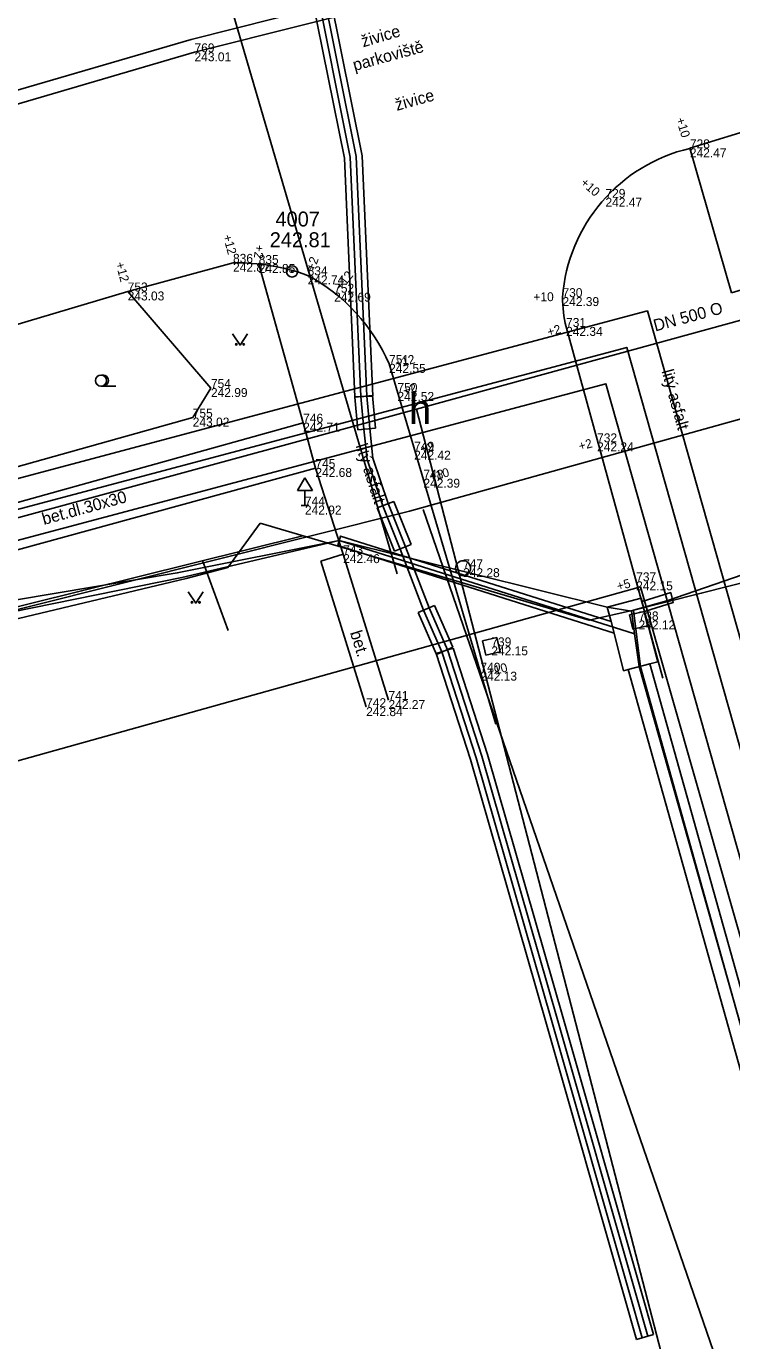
# Model space of a CAD drawing. Extents: x -599432 to -598680, y -1159407 to -1158632.
# Drawn here: x -599111.08 to -599087.44, y -1158969.78 to -1158925.7 of the extents above; entities that cross this region are included whole.
import ezdxf

# ---------------------------------------------------------------- set-up
doc = ezdxf.new("R2010")
doc.units = 0
for name, color, linetype in [('0001 VY - Body PBP', 7, 'Continuous'), ('0002 VY - Body PBP - čísla', 7, 'Continuous'), ('0003 VY - Body PBP - výšky', 7, 'Continuous'), ('0004 VY - Body podrobné', 7, 'Continuous'), ('0005 VY - Body podrobné - čísla', 7, 'Continuous'), ('0006 VY - Body podrobné - výšky', 7, 'Continuous'), ('0024 ZA - Podezdívka', 7, 'Continuous'), ('0025 ZA - Opěrná zeď', 7, 'Continuous'), ('0027 ZA - Silnice_cesta zpevněná', 7, 'Continuous'), ('0030 ZA - Chodník', 7, 'Continuous'), ('0031 ZA - Ostatní rozhraní', 7, 'Continuous'), ('0032 TE - Popis povrchu', 7, 'Continuous'), ('0034 ZA - Kultury - značky', 7, 'Continuous'), ('0038 ZA - Hranice souvislého porostu', 7, 'Continuous'), ('0062 ZA - Doprava - dopravní značky', 7, 'Continuous'), ('0073 TE - Výška obrubníků a zdí', 7, 'Continuous'), ('0074 TE - Vysvětlivky', 7, 'Continuous'), ('0075 ZA - BVK - kanalizace - buňky', 7, 'Continuous'), ('0200 PV - BVK - kanalizace - buňky', 7, 'Continuous'), ('0201 PV - BVK - kanalizace - popis', 7, 'Continuous'), ('0206 PV - BVK - kanalizace - jednotná', 7, 'Continuous'), ('0214 PV - BVK - vodovod - pitná', 7, 'Continuous'), ('0221 PV - BVK - vodovod - zrušený', 7, 'Continuous'), ('0254 PV - TB - horkovod - vedení', 7, 'Continuous'), ('0255 PV - TB - horkovod - okraj', 7, 'Continuous'), ('0354 PV - EON - VN', 7, 'Continuous'), ('0367 PV - EON - VN chránička', 7, 'Continuous'), ('0454 PV - O2 - kabel zaměřený', 7, 'Continuous'), ('0455 PV - O2 - kabel nezaměřený', 7, 'Continuous'), ('0457 PV - O2 - kabelovod', 7, 'Continuous'), ('0502 PV - UPC - vedení', 7, 'Continuous'), ('0550 PV - UPC - přípojka', 7, 'Continuous'), ('0552 PV - OT VUT', 7, 'Continuous'), ('0602 PV - FASTER', 7, 'Continuous'), ('0703 PV - DIAL TELECOM optický kabel', 7, 'Continuous'), ('0750 ZA - nerozlišené sítě - buňky', 7, 'Continuous')]:
    doc.layers.add(name, color=color, linetype=linetype)

msp = doc.modelspace()

# ---------------------------------------------------------------- linework, layer by layer
at = {"layer": '0001 VY - Body PBP'}
for radius in [0.188, 0.00896]:
    msp.add_circle((-599102.17, -1158933.92), radius, dxfattribs=at)
at = {"layer": '0004 VY - Body podrobné'}
for p, q in [((-599105.44, -1158926.57), (-599105.44, -1158926.57)), ((-599088.84, -1158929.79), (-599088.84, -1158929.79)), ((-599091.67, -1158931.45), (-599091.67, -1158931.45)), ((-599104.15, -1158933.63), (-599104.15, -1158933.63)), ((-599103.29, -1158933.67), (-599103.29, -1158933.67)), ((-599101.65, -1158934.05), (-599101.65, -1158934.05)), ((-599107.68, -1158934.59), (-599107.68, -1158934.59)), ((-599100.76, -1158934.63), (-599100.76, -1158934.63)), ((-599093.11, -1158934.78), (-599093.11, -1158934.78)), ((-599087.45, -1158934.64), (-599087.45, -1158934.64)), ((-599092.99, -1158935.78), (-599092.99, -1158935.78)), ((-599098.92, -1158937.02), (-599098.92, -1158937.02)), ((-599104.89, -1158937.83), (-599104.89, -1158937.83)), ((-599098.64, -1158937.96), (-599098.64, -1158937.96)), ((-599105.5, -1158938.82), (-599105.5, -1158938.82)), ((-599101.8, -1158938.99), (-599101.8, -1158938.99)), ((-599091.95, -1158939.65), (-599091.95, -1158939.65)), ((-599098.08, -1158939.93), (-599098.08, -1158939.93)), ((-599101.39, -1158940.51), (-599101.39, -1158940.51)), ((-599097.77, -1158940.87), (-599097.77, -1158940.87)), ((-599101.74, -1158941.77), (-599101.74, -1158941.77)), ((-599100.46, -1158943.4), (-599100.46, -1158943.4)), ((-599096.44, -1158943.87), (-599096.44, -1158943.87)), ((-599090.64, -1158944.31), (-599090.64, -1158944.31)), ((-599090.56, -1158945.621), (-599090.56, -1158945.621)), ((-599095.494, -1158946.491), (-599095.494, -1158946.491)), ((-599095.86, -1158947.34), (-599095.86, -1158947.34)), ((-599099.69, -1158948.53), (-599099.69, -1158948.53)), ((-599098.94, -1158948.29), (-599098.94, -1158948.29))]:
    msp.add_line(p, q, dxfattribs=at)
at = {"layer": '0024 ZA - Podezdívka'}
for p, q in [((-599105.558, -1158926.136), (-599091.888, -1158922.688)), ((-599105.44, -1158926.57), (-599091.76, -1158923.12)), ((-599126.554, -1158932.267), (-599105.558, -1158926.136)), ((-599126.43, -1158932.7), (-599105.44, -1158926.57)), ((-599100.46, -1158943.4), (-599101.212, -1158943.634)), ((-599099.692, -1158948.524), (-599101.212, -1158943.634))]:
    msp.add_line(p, q, dxfattribs=at)
at = {"layer": '0025 ZA - Opěrná zeď'}
msp.add_line((-599098.94, -1158948.29), (-599100.46, -1158943.4), dxfattribs=at)
at = {"layer": '0027 ZA - Silnice_cesta zpevněná'}
for p, q in [((-599088.84, -1158929.79), (-599085.81, -1158928.85)), ((-599104.15, -1158933.63), (-599107.68, -1158934.59)), ((-599107.68, -1158934.59), (-599123.38, -1158939.28)), ((-599089.746, -1158947.557), (-599092.99, -1158935.78)), ((-599095.341, -1158949.098), (-599098.92, -1158937.02))]:
    msp.add_line(p, q, dxfattribs=at)
for centre, radius, start, end in [((-599087.569, -1158935.2), 5.557, 103.226, 175.6661), ((-599104.046, -1158940.662), 7.033, 70.0807, 90.846), ((-599104.522, -1158939.429), 6.098, 23.2724, 61.9055), ((-599088.614, -1158934.748), 4.496, 180.4114, 193.2742)]:
    msp.add_arc(centre, radius, start, end, dxfattribs=at)
at = {"layer": '0030 ZA - Chodník'}
for p, q in [((-599088.84, -1158929.79), (-599087.45, -1158934.64)), ((-599087.45, -1158934.64), (-599081.43, -1158932.81)), ((-599103.29, -1158933.67), (-599101.8, -1158938.99)), ((-599101.8, -1158938.99), (-599121.78, -1158944.56)), ((-599121.3, -1158945.99), (-599101.39, -1158940.51)), ((-599101.39, -1158940.51), (-599100.46, -1158943.4))]:
    msp.add_line(p, q, dxfattribs=at)
at = {"layer": '0031 ZA - Ostatní rozhraní'}
msp.add_line((-599101.8, -1158938.99), (-599101.39, -1158940.51), dxfattribs=at)
at = {"layer": '0034 ZA - Kultury - značky'}
msp.add_line((-599108.574, -1158937.767), (-599108.074, -1158937.767), dxfattribs=at)
for points in [[(-599104.164, -1158936.012), (-599103.914, -1158936.387), (-599103.664, -1158936.012)], [(-599105.649, -1158944.662), (-599105.399, -1158945.037), (-599105.149, -1158944.662)]]:
    msp.add_lwpolyline(points, dxfattribs=at)
for centre, radius in [((-599104.039, -1158936.362), 0.025), ((-599103.789, -1158936.362), 0.025), ((-599108.574, -1158937.579), 0.187), ((-599105.524, -1158945.012), 0.025), ((-599105.274, -1158945.012), 0.025)]:
    msp.add_circle(centre, radius, dxfattribs=at)
msp.add_arc((-599108.511, -1158937.579), 0.187, 260.4059, 99.5941, dxfattribs=at)
at = {"layer": '0038 ZA - Hranice souvislého porostu'}
for p, q in [((-599104.89, -1158937.83), (-599107.68, -1158934.59)), ((-599105.5, -1158938.82), (-599104.89, -1158937.83)), ((-599120.95, -1158943.15), (-599105.5, -1158938.82))]:
    msp.add_line(p, q, dxfattribs=at)
at = {"layer": '0062 ZA - Doprava - dopravní značky'}
for p, q in [((-599101.74, -1158940.837), (-599101.99, -1158941.27)), ((-599101.74, -1158940.837), (-599101.49, -1158941.27)), ((-599101.99, -1158941.27), (-599101.49, -1158941.27)), ((-599101.74, -1158941.77), (-599101.74, -1158941.27)), ((-599101.865, -1158941.77), (-599101.615, -1158941.77))]:
    msp.add_line(p, q, dxfattribs=at)
at = {"layer": '0075 ZA - BVK - kanalizace - buňky'}
msp.add_circle((-599096.44, -1158943.87), 0.25, dxfattribs=at)
at = {"layer": '0206 PV - BVK - kanalizace - jednotná'}
for p, q in [((-599098.005, -1158938.54), (-599055.379, -1158926.835)), ((-599098.005, -1158938.54), (-599055.379, -1158926.835)), ((-599179.749, -1158960.781), (-599098.005, -1158938.54)), ((-599179.749, -1158960.781), (-599098.005, -1158938.54)), ((-599076.442, -1159021.7), (-599098.005, -1158938.54)), ((-599076.442, -1159021.7), (-599098.005, -1158938.54))]:
    msp.add_line(p, q, dxfattribs=at)
at = {"layer": '0214 PV - BVK - vodovod - pitná'}
msp.add_lwpolyline([(-599224.534, -1158936.87), (-599222.42, -1158945.16), (-599215.18, -1158973.1), (-599214.01, -1158973.78), (-599152.34, -1158956.416), (-599150.65, -1158955.95), (-599117.576, -1158946.804), (-599098.24, -1158941.96), (-599043.28, -1158926.64)], dxfattribs=at)
at = {"layer": '0221 PV - BVK - vodovod - zrušený'}
msp.add_lwpolyline([(-599097.773, -1158941.904), (-599077.43, -1159000.97), (-599067.48, -1159031.6), (-599066.02, -1159033.24), (-599064.703, -1159032.861)], dxfattribs=at)
at = {"layer": '0254 PV - TB - horkovod - vedení'}
msp.add_lwpolyline([(-599117.439, -1158943.513), (-599090.959, -1158936.465), (-599075.067, -1158992.646)], dxfattribs=at)
at = {"layer": '0255 PV - TB - horkovod - okraj'}
for points in [[(-599116.73, -1158942.29), (-599090.265, -1158935.245), (-599074.268, -1158991.797)], [(-599118.148, -1158944.736), (-599091.653, -1158937.685), (-599076.029, -1158992.918)]]:
    msp.add_lwpolyline(points, dxfattribs=at)
at = {"layer": '0354 PV - EON - VN'}
for points in [[(-599145.481, -1158921.466), (-599140.483, -1158919.816), (-599136.355, -1158918.837), (-599130.655, -1158917.267), (-599126.136, -1158916.177), (-599122.299, -1158915.198), (-599120.36, -1158914.878), (-599115.595, -1158913.737), (-599111.233, -1158912.526), (-599109.544, -1158912.057), (-599106.208, -1158911.199), (-599105.476, -1158911.584), (-599104.034, -1158916.175), (-599102.994, -1158918.604), (-599101.447, -1158923.974), (-599100.22, -1158930.092), (-599099.87, -1158938.117), (-599099.769, -1158939.21), (-599099.658, -1158940.222)], [(-599099.462, -1158940.178), (-599099.571, -1158939.19), (-599099.67, -1158938.103), (-599100.02, -1158930.068), (-599101.253, -1158923.926)], [(-599099.658, -1158940.222), (-599099.134, -1158941.775), (-599098.553, -1158943.227), (-599097.763, -1158945.278), (-599097.154, -1158946.675), (-599096.006, -1158950.229), (-599093.456, -1158959.108), (-599090.856, -1158968.227), (-599090.443, -1158969.676)], [(-599090.251, -1158969.62), (-599090.664, -1158968.173), (-599093.264, -1158959.052), (-599095.814, -1158950.171), (-599096.966, -1158946.605), (-599097.577, -1158945.202), (-599098.367, -1158943.153), (-599098.946, -1158941.705), (-599099.462, -1158940.178)]]:
    msp.add_lwpolyline(points, dxfattribs=at)
at = {"layer": '0367 PV - EON - VN chránička'}
for p, q in [((-599101.058, -1158923.879), (-599099.821, -1158930.044)), ((-599100.419, -1158930.116), (-599101.642, -1158924.021)), ((-599100.07, -1158938.123), (-599100.419, -1158930.116)), ((-599099.821, -1158930.044), (-599099.47, -1158938.097)), ((-599099.47, -1158938.097), (-599100.07, -1158938.123)), ((-599100.069, -1158938.137), (-599099.471, -1158938.083)), ((-599099.471, -1158938.083), (-599099.371, -1158939.173)), ((-599099.969, -1158939.227), (-599100.069, -1158938.137)), ((-599099.371, -1158939.173), (-599099.969, -1158939.227)), ((-599099.319, -1158941.851), (-599098.761, -1158941.629)), ((-599098.761, -1158941.629), (-599098.181, -1158943.079)), ((-599098.739, -1158943.301), (-599099.319, -1158941.851)), ((-599098.181, -1158943.079), (-599098.739, -1158943.301)), ((-599097.945, -1158945.36), (-599097.395, -1158945.12)), ((-599097.395, -1158945.12), (-599096.785, -1158946.52)), ((-599097.335, -1158946.76), (-599097.945, -1158945.36)), ((-599097.345, -1158946.732), (-599096.775, -1158946.548)), ((-599096.197, -1158950.288), (-599097.345, -1158946.732)), ((-599096.785, -1158946.52), (-599097.335, -1158946.76)), ((-599096.775, -1158946.548), (-599095.623, -1158950.112)), ((-599093.648, -1158959.163), (-599096.197, -1158950.288)), ((-599095.623, -1158950.112), (-599093.072, -1158958.997)), ((-599091.048, -1158968.282), (-599093.648, -1158959.163)), ((-599093.072, -1158958.997), (-599090.472, -1158968.118)), ((-599090.635, -1158969.733), (-599091.048, -1158968.282)), ((-599090.472, -1158968.118), (-599090.059, -1158969.563)), ((-599090.059, -1158969.563), (-599090.635, -1158969.733))]:
    msp.add_line(p, q, dxfattribs=at)
at = {"layer": '0454 PV - O2 - kabel zaměřený'}
for points in [[(-599090.81, -1158945.3), (-599089.61, -1158944.96), (-599085.79, -1158943.64), (-599084.6, -1158943.24), (-599080.93, -1158942.08), (-599071.4, -1158939.5), (-599061.49, -1158936.96), (-599054.83, -1158935.45), (-599045.65, -1158933), (-599044.96, -1158932.36), (-599035.85, -1158930), (-599034.92, -1158929.67), (-599030.38, -1158928.49), (-599029.53, -1158928.8), (-599028.18, -1158932.86)], [(-599090.81, -1158945.3), (-599088.46, -1158944.71), (-599084.75, -1158943.77), (-599054.42, -1158935.31), (-599035.73, -1158930.27), (-599032.25, -1158929.33), (-599029.5, -1158928.59)], [(-599120.995, -1158946.541), (-599106.02, -1158944.03), (-599100.59, -1158942.94)], [(-599120.83, -1158947.22), (-599105.86, -1158944.18), (-599100.59, -1158942.94)], [(-599090.802, -1158945.306), (-599091.61, -1158945.18), (-599100.59, -1158942.94)], [(-599089.61, -1158944.96), (-599085.79, -1158943.64)], [(-599088.46, -1158944.71), (-599084.75, -1158943.77)]]:
    msp.add_lwpolyline(points, dxfattribs=at)
at = {"layer": '0455 PV - O2 - kabel nezaměřený'}
for points in [[(-599100.59, -1158942.94), (-599090.7, -1158946.07)], [(-599090.7, -1158946.07), (-599090.802, -1158945.306)], [(-599076.21, -1158997.85), (-599090.54, -1158947.17), (-599090.7, -1158946.07)]]:
    msp.add_lwpolyline(points, dxfattribs=at)
at = {"layer": '0457 PV - O2 - kabelovod'}
for points in [[(-599091.38, -1158946.05), (-599100.64, -1158943.114), (-599100.548, -1158942.791), (-599091.48, -1158945.66)], [(-599090.44, -1158944.99), (-599089.48, -1158944.69), (-599089.4, -1158945.02), (-599090.36, -1158945.32)], [(-599090.44, -1158944.99), (-599090.47, -1158944.88), (-599091.61, -1158945.18), (-599091.48, -1158945.66)], [(-599090.44, -1158944.99), (-599090.36, -1158945.32)], [(-599090.18, -1158947.08), (-599089.92, -1158947.01), (-599090.36, -1158945.32)], [(-599091.48, -1158945.66), (-599091.38, -1158946.05)], [(-599090.91, -1158947.27), (-599091.06, -1158947.31), (-599091.38, -1158946.05)], [(-599090.18, -1158947.08), (-599090.91, -1158947.27)], [(-599090.91, -1158947.27), (-599077.35, -1158995.67)], [(-599090.18, -1158947.08), (-599076.63, -1158995.46)]]:
    msp.add_lwpolyline(points, dxfattribs=at)
at = {"layer": '0502 PV - UPC - vedení'}
msp.add_lwpolyline([(-599183.08, -1158973.78), (-599174.33, -1158971.03), (-599173.51, -1158971.23), (-599169.96, -1158969.79), (-599165.49, -1158965.49), (-599150.07, -1158961.13), (-599148.31, -1158956.97), (-599146.81, -1158954.85), (-599144.21, -1158953.32), (-599101.81, -1158942.78)], dxfattribs=at)
at = {"layer": '0550 PV - UPC - přípojka'}
msp.add_line((-599104.31, -1158945.96), (-599105.175, -1158943.617), dxfattribs=at)
at = {"layer": '0552 PV - OT VUT'}
for points in [[(-599114.02, -1158946.19), (-599105.72, -1158944.22), (-599104.32, -1158943.85), (-599103.24, -1158942.36)], [(-599114.02, -1158946.19), (-599105.72, -1158944.22), (-599104.32, -1158943.85), (-599103.24, -1158942.36)], [(-599103.24, -1158942.36), (-599092.212, -1158945.615), (-599090.729, -1158945.277), (-599090.491, -1158947.18), (-599076.99, -1158995.57), (-599076.47, -1158996.83), (-599075.969, -1158997.8), (-599069.57, -1159019.61), (-599068.76, -1159021.27), (-599067.32, -1159020.79), (-599063.371, -1159019.665)], [(-599103.24, -1158942.36), (-599092.212, -1158945.615), (-599090.729, -1158945.277), (-599090.491, -1158947.18), (-599076.99, -1158995.57), (-599076.47, -1158996.83), (-599075.969, -1158997.8), (-599069.57, -1159019.61), (-599068.76, -1159021.27), (-599067.32, -1159020.79), (-599063.371, -1159019.665)]]:
    msp.add_lwpolyline(points, dxfattribs=at)
at = {"layer": '0602 PV - FASTER'}
msp.add_lwpolyline([(-599170.14, -1158969.8), (-599168.81, -1158968.65), (-599165.57, -1158965.49), (-599090.5, -1158944.5), (-599067.02, -1159026.87), (-599065.096, -1159026.325)], dxfattribs=at)
at = {"layer": '0703 PV - DIAL TELECOM optický kabel'}
msp.add_line((-599107.768, -1158912.907), (-599098.65, -1158944.06), dxfattribs=at)
at = {"layer": '0750 ZA - nerozlišené sítě - buňky'}
for p, q in [((-599090.373, -1158945.321), (-599090.86, -1158945.433)), ((-599090.86, -1158945.433), (-599090.748, -1158945.92)), ((-599090.26, -1158945.808), (-599090.373, -1158945.321)), ((-599090.748, -1158945.92), (-599090.26, -1158945.808)), ((-599095.307, -1158946.191), (-599095.794, -1158946.304)), ((-599095.794, -1158946.304), (-599095.681, -1158946.791)), ((-599095.194, -1158946.678), (-599095.307, -1158946.191)), ((-599095.681, -1158946.791), (-599095.194, -1158946.678))]:
    msp.add_line(p, q, dxfattribs=at)

# ---------------------------------------------------------------- texts
at = {"layer": '0002 VY - Body PBP - čísla'}
msp.add_text('4007', height=0.5, dxfattribs=at).set_placement((-599102.727, -1158932.411))
at = {"layer": '0003 VY - Body PBP - výšky'}
msp.add_text('242.81', height=0.5, dxfattribs=at).set_placement((-599102.92, -1158933.105))
at = {"layer": '0005 VY - Body podrobné - čísla'}
for s, p in [('769', (-599105.44, -1158926.57)), ('728', (-599088.84, -1158929.79)), ('729', (-599091.67, -1158931.45)), ('836', (-599104.15, -1158933.63)), ('835', (-599103.29, -1158933.67)), ('834', (-599101.65, -1158934.05)), ('753', (-599107.68, -1158934.59)), ('752', (-599100.76, -1158934.63)), ('730', (-599093.11, -1158934.78)), ('731', (-599092.99, -1158935.78)), ('751', (-599098.92, -1158937.02)), ('754', (-599104.89, -1158937.83)), ('750', (-599098.64, -1158937.96)), ('755', (-599105.5, -1158938.82)), ('746', (-599101.8, -1158938.99)), ('732', (-599091.95, -1158939.65)), ('749', (-599098.08, -1158939.93)), ('745', (-599101.39, -1158940.51)), ('748', (-599097.77, -1158940.87)), ('744', (-599101.74, -1158941.77)), ('743', (-599100.46, -1158943.4)), ('747', (-599096.44, -1158943.87)), ('737', (-599090.64, -1158944.31)), ('738', (-599090.56, -1158945.621)), ('739', (-599095.494, -1158946.491)), ('740', (-599095.86, -1158947.34)), ('742', (-599099.69, -1158948.53)), ('741', (-599098.94, -1158948.29))]:
    msp.add_text(s, height=0.3, dxfattribs=at).set_placement(p)
at = {"layer": '0006 VY - Body podrobné - výšky'}
for s, p in [('243.01', (-599105.44, -1158926.87)), ('242.47', (-599088.84, -1158930.09)), ('242.47', (-599091.67, -1158931.75)), ('242.87', (-599104.15, -1158933.93)), ('242.85', (-599103.29, -1158933.97)), ('242.74', (-599101.65, -1158934.35)), ('243.03', (-599107.68, -1158934.89)), ('242.69', (-599100.76, -1158934.93)), ('242.39', (-599093.11, -1158935.08)), ('242.34', (-599092.99, -1158936.08)), ('242.55', (-599098.92, -1158937.32)), ('242.99', (-599104.89, -1158938.13)), ('242.52', (-599098.64, -1158938.26)), ('243.02', (-599105.5, -1158939.12)), ('242.71', (-599101.8, -1158939.29)), ('242.24', (-599091.95, -1158939.95)), ('242.42', (-599098.08, -1158940.23)), ('242.68', (-599101.39, -1158940.81)), ('242.39', (-599097.77, -1158941.17)), ('242.92', (-599101.74, -1158942.07)), ('242.46', (-599100.46, -1158943.7)), ('242.28', (-599096.44, -1158944.17)), ('242.15', (-599090.64, -1158944.61)), ('242.12', (-599090.56, -1158945.921)), ('242.15', (-599095.494, -1158946.791)), ('242.13', (-599095.86, -1158947.64)), ('242.84', (-599099.69, -1158948.83)), ('242.27', (-599098.94, -1158948.59))]:
    msp.add_text(s, height=0.3, dxfattribs=at).set_placement(p)
at = {"layer": '0032 TE - Popis povrchu'}
for s, rotation, p in [('živice', 16.5788, (-599099.789, -1158926.405)), ('živice', 15.5236, (-599098.659, -1158928.535)), ('litý asfalt', 285.4028, (-599089.791, -1158937.261)), ('litý asfalt', 287.8381, (-599100.045, -1158939.763)), ('bet.dl.30x30', 15.389, (-599110.488, -1158942.422)), ('bet.', 287.2673, (-599100.234, -1158946.029))]:
    msp.add_text(s, height=0.4, rotation=rotation, dxfattribs=at).set_placement(p)
at = {"layer": '0073 TE - Výška obrubníků a zdí'}
for s, rotation, p in [('+10', 287.2355, (-599089.312, -1158928.808)), ('+10', 319.5394, (-599092.532, -1158930.984)), ('+12', 285.2139, (-599104.492, -1158932.725)), ('+2', 263.3709, (-599103.4, -1158933.012)), ('+12', 285.2139, (-599108.091, -1158933.645)), ('+2', 70.3245, (-599101.428, -1158933.923)), ('+12', 51.8019, (-599100.52, -1158934.587)), ('+10', 0.8152, (-599094.082, -1158934.925)), ('+2', 15.4028, (-599093.577, -1158936.102)), ('+12', 15.4028, (-599098.678, -1158937.168)), ('+2', 15.4028, (-599098.413, -1158938.072)), ('+2', 15.4028, (-599097.832, -1158940.041)), ('+2', 15.4028, (-599092.524, -1158939.931)), ('+10', 15.4028, (-599097.535, -1158940.963)), ('+5', 15.4028, (-599091.244, -1158944.627)), ('+10', 15.4028, (-599095.583, -1158947.507))]:
    msp.add_text(s, height=0.3, rotation=rotation, dxfattribs=at).set_placement(p)
at = {"layer": '0074 TE - Vysvětlivky'}
msp.add_text('parkoviště', height=0.4, rotation=15.4635, dxfattribs=at).set_placement((-599100.076, -1158927.199))
at = {"layer": '0200 PV - BVK - kanalizace - buňky'}
msp.add_text('h', height=1, dxfattribs=at).set_placement((-599098.255, -1158939.04))
at = {"layer": '0201 PV - BVK - kanalizace - popis'}
msp.add_text('DN 500 O', height=0.4, rotation=15, dxfattribs=at).set_placement((-599090.002, -1158935.934))

doc.saveas('drawing.dxf')
